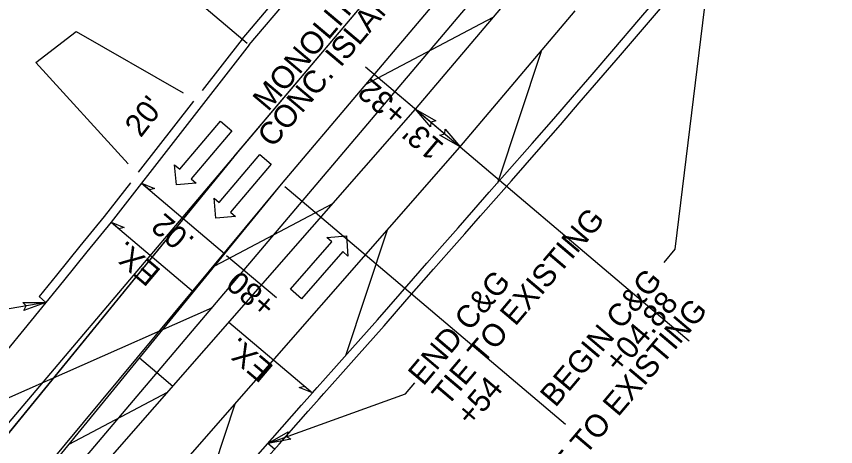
# Model space of a CAD drawing. Extents: x 1761082 to 1764358, y 421907 to 425434.
# Drawn here: x 1762006.6 to 1762189, y 422771.8 to 422867.6 of the extents above; entities that cross this region are included whole.
import ezdxf

# ---------------------------------------------------------------- set-up
doc = ezdxf.new("R2010")
doc.units = 0
for name, color, linetype in [('MARK HOOKS CENTER STRAIGHT LEFT TURN ARROW CELL', 7, 'Continuous'), ('MARK LEFT TURN ARROW CELL', 7, 'Continuous'), ('MARK ONLY WORD SYMBOL CELL', 7, 'Continuous'), ('MARK STRAIGHT RIGHT ARROW CELL', 7, 'Continuous'), ('MARK UTURN ARROW CELL', 7, 'Continuous'), ('Prop Conc Driveway', 7, 'Continuous'), ('Prop Mkg 3ft Min Skp 3ft Wide White', 7, 'Continuous'), ('Prop Mkg 3ft Min Skp 9ft Wide White', 7, 'Continuous'), ('Prop Mkg Min Skp 6ft Yellow', 7, 'Continuous'), ('Prop Mkg Skp Wht', 7, 'Continuous'), ('Prop Mkg Solid White Multiple Diagonals V8i', 7, 'Continuous'), ('Prop Mkg Solid Yel Skip LT', 7, 'Continuous'), ('Prop Mkg Solid Yel Skip RT', 7, 'Continuous'), ('Prop Mkg Solid Yellow Diagonals', 7, 'Continuous'), ('Prop Mkg Solid Yellow Edge Line', 7, 'Continuous'), ('Prop Mkg Solid Yellow Lane Line', 7, 'Continuous'), ('Scratch_Level_0', 7, 'Continuous'), ('Scratch_Level_5', 7, 'Continuous')]:
    doc.layers.add(name, color=color, linetype=linetype)

msp = doc.modelspace()

# ---------------------------------------------------------------- linework, layer by layer
at = {"layer": 'MARK HOOKS CENTER STRAIGHT LEFT TURN ARROW CELL'}
msp.add_line((1762070.2, 422826.39), (1762066.38, 422829.62), dxfattribs=at)
at = {"layer": 'MARK LEFT TURN ARROW CELL'}
for p, q in [((1762056.89, 422862.51), (1762067.26, 422874.75)), ((1762056.89, 422862.51), (1762047.97, 422851.06)), ((1762031.99, 422830.55), (1762026.12, 422823.02)), ((1762013.19, 422803.91), (1762011.66, 422805.21)), ((1762064.09, 422771.27), (1762062.57, 422772.56))]:
    msp.add_line(p, q, dxfattribs=at)
msp.add_lwpolyline([(1762026.12, 422823.02), (1762020.74, 422816.45), (1762015.52, 422809.98), (1762011.66, 422805.21)], dxfattribs=at)
at = {"layer": 'MARK ONLY WORD SYMBOL CELL'}
msp.add_line((1762033.83, 422832.91), (1762046.12, 422848.69), dxfattribs=at)
at = {"layer": 'MARK STRAIGHT RIGHT ARROW CELL'}
msp.add_line((1761294.53, 421910.78), (1762672.97, 423537.92), dxfattribs=at)
at = {"layer": 'MARK UTURN ARROW CELL'}
msp.add_lwpolyline([(1762050.16, 422802.74), (1761885.75, 422730.03), (1761804.33, 422633.93)], dxfattribs=at)
at = {"layer": 'Prop Conc Driveway'}
for p, q in [((1762010.93, 422857.29), (1762019.93, 422864.21)), ((1762019.93, 422864.21), (1762043.76, 422850.54)), ((1762031.47, 422834.76), (1762010.93, 422857.29))]:
    msp.add_line(p, q, dxfattribs=at)
at = {"layer": 'Prop Mkg 3ft Min Skp 3ft Wide White'}
msp.add_line((1761294.53, 421910.78), (1762672.97, 423537.92), dxfattribs=at)
at = {"layer": 'Prop Mkg 3ft Min Skp 9ft Wide White'}
for points in [[(1762074.01, 422782.47), (1762075.07, 422783.67), (1762078.74, 422787.78), (1762082.33, 422791.8), (1762088.47, 422798.73), (1762093.54, 422804.54), (1762099.47, 422811.3), (1762102.88, 422815.18), (1762106.42, 422819.2), (1762109.92, 422823.18), (1762113.38, 422827.1), (1762116.8, 422830.99), (1762122.94, 422837.96), (1762127.73, 422843.46), (1762131.92, 422848.3), (1762136.29, 422853.34), (1762141.13, 422858.95), (1762152.67, 422872.49)], [(1762006.07, 422705.23), (1762010.45, 422710.2), (1762014.62, 422714.93), (1762018.46, 422719.3), (1762021.98, 422723.3), (1762028.23, 422730.42), (1762034.5, 422737.58), (1762041.01, 422745.03), (1762044.41, 422748.92), (1762047.93, 422752.93), (1762051.57, 422757.05), (1762055.18, 422761.15), (1762058.64, 422765.08), (1762065.09, 422772.41), (1762071.58, 422779.74), (1762074.01, 422782.47)]]:
    msp.add_lwpolyline(points, dxfattribs=at)
at = {"layer": 'Prop Mkg Skp Wht'}
for q in [(1762092.94, 422901.97), (1762027.69, 422821.77)]:
    msp.add_line((1762058.44, 422861.25), q, dxfattribs=at)
for points in [[(1762072.51, 422783.8), (1762073.58, 422785), (1762077.25, 422789.11), (1762080.84, 422793.13), (1762086.97, 422800.06), (1762092.04, 422805.85), (1762097.97, 422812.62), (1762101.38, 422816.5), (1762104.92, 422820.52), (1762108.42, 422824.5), (1762111.88, 422828.43), (1762115.3, 422832.31), (1762121.43, 422839.28), (1762126.22, 422844.77), (1762130.41, 422849.61), (1762134.78, 422854.65), (1762139.61, 422860.25), (1762145.2, 422866.81), (1762151.14, 422873.79), (1762157.03, 422880.67), (1762161.8, 422886.24)], [(1762027.69, 422821.77), (1762022.3, 422815.19), (1762017.07, 422808.73), (1762011.57, 422801.92), (1762008.28, 422797.88), (1762004.62, 422793.41)], [(1762004.57, 422706.55), (1762008.95, 422711.52), (1762013.12, 422716.25), (1762016.96, 422720.62), (1762020.47, 422724.62), (1762026.72, 422731.74), (1762032.99, 422738.9), (1762039.5, 422746.35), (1762042.91, 422750.24), (1762046.43, 422754.25), (1762050.07, 422758.38), (1762053.68, 422762.47), (1762057.14, 422766.4), (1762063.59, 422773.73), (1762070.08, 422781.07), (1762072.51, 422783.8)]]:
    msp.add_lwpolyline(points, dxfattribs=at)
at = {"layer": 'Prop Mkg Solid White Multiple Diagonals V8i'}
for p, q in [((1761636.39, 422342), (1762107.89, 422898.74)), ((1762156.41, 422795.29), (1762090.88, 422850.81)), ((1761847.66, 422582.27), (1762056.32, 422837.86)), ((1761650.04, 422330.43), (1762065.62, 422830.27)), ((1762128.83, 422776.72), (1762070.2, 422826.39))]:
    msp.add_line(p, q, dxfattribs=at)
at = {"layer": 'Prop Mkg Solid Yel Skip RT'}
for p, q in [((1762037.29, 422879.17), (1762057.99, 422861.63)), ((1762084.34, 422856.34), (1762094.68, 422847.59)), ((1762095.46, 422846.93), (1762105.38, 422838.52)), ((1762053.42, 422814.39), (1762064.49, 422805.01))]:
    msp.add_line(p, q, dxfattribs=at)
for points in [[(1762161.8, 422886.24), (1762153.19, 422815.74), (1762150.72, 422812.83)], [(1762013.19, 422803.91), (1761904.06, 422785.03), (1761901.46, 422781.96)], [(1762062.57, 422772.56), (1762093.26, 422783.58), (1762095.3, 422785.99)]]:
    msp.add_lwpolyline(points, dxfattribs=at)
at = {"layer": 'Prop Mkg Solid Yellow Diagonals'}
for p, q in [((1762042.97, 422833.57), (1762052.03, 422844.24)), ((1762052.03, 422844.24), (1762054.55, 422842.1)), ((1762054.55, 422842.1), (1762045.49, 422831.43)), ((1762051.76, 422826.15), (1762060.82, 422836.82)), ((1762060.82, 422836.82), (1762063.34, 422834.69)), ((1762042.23, 422830.06), (1762041.83, 422834.54)), ((1762041.83, 422834.54), (1762042.97, 422833.57)), ((1762063.34, 422834.69), (1762054.28, 422824.02)), ((1762045.49, 422831.43), (1762046.63, 422830.46)), ((1762046.63, 422830.46), (1762042.23, 422830.06)), ((1762051.02, 422822.65), (1762050.62, 422827.12)), ((1762050.62, 422827.12), (1762051.76, 422826.15)), ((1762054.28, 422824.02), (1762055.42, 422823.04)), ((1762055.42, 422823.04), (1762051.02, 422822.65)), ((1762075.7, 422818.4), (1762080.1, 422818.72)), ((1762075.7, 422818.4), (1762080.1, 422818.72)), ((1762076.82, 422817.41), (1762075.7, 422818.4)), ((1762076.82, 422817.41), (1762075.7, 422818.4)), ((1762080.1, 422818.72), (1762080.43, 422814.24)), ((1762080.1, 422818.72), (1762080.43, 422814.24)), ((1762067.6, 422806.88), (1762076.82, 422817.41)), ((1762067.6, 422806.88), (1762076.82, 422817.41)), ((1762079.31, 422815.23), (1762070.08, 422804.71)), ((1762079.31, 422815.23), (1762070.08, 422804.71)), ((1762080.43, 422814.24), (1762079.31, 422815.23)), ((1762080.43, 422814.24), (1762079.31, 422815.23)), ((1762070.08, 422804.71), (1762067.6, 422806.88)), ((1762070.08, 422804.71), (1762067.6, 422806.88))]:
    msp.add_line(p, q, dxfattribs=at)
at = {"layer": 'Prop Mkg Solid Yellow Edge Line'}
for q in [(1762107.89, 422898.74), (1761848.88, 422583.77)]:
    msp.add_line((1762055.03, 422836.33), q, dxfattribs=at)
at = {"layer": 'Prop Mkg Solid Yellow Lane Line'}
for points in [[(1762098.78, 422842.96), (1762095.46, 422846.93), (1762099.96, 422844.3), (1762098.88, 422844.03)], [(1762102.05, 422842.49), (1762105.38, 422838.52), (1762100.88, 422841.15), (1762101.96, 422841.42)], [(1762008.01, 422803.91), (1762013.19, 422803.91), (1762008.29, 422802.14), (1762008.77, 422803.15)], [(1762067.67, 422773.46), (1762062.57, 422772.56), (1762067.09, 422775.15), (1762066.78, 422774.08)]]:
    msp.add_lwpolyline(points, close=True, dxfattribs=at)
at = {"layer": 'Scratch_Level_0'}
for p, q in [((1762065.62, 422830.27), (1762144.83, 422923.77)), ((1762095.46, 422846.93), (1762127.21, 422884.4)), ((1762084.36, 422852.39), (1762112.78, 422867.37)), ((1762105.31, 422838.44), (1762131, 422868.77)), ((1762123.4, 422859.79), (1762113.68, 422830.47)), ((1761856.89, 422574.6), (1762095.46, 422846.93)), ((1761842.22, 422538.12), (1762105.31, 422838.44)), ((1761856.89, 422574.6), (1762065.62, 422830.27)), ((1762050.77, 422812.08), (1762077.08, 422825.95)), ((1762089.13, 422819.98), (1762079.88, 422792.06)), ((1762037.88, 422788.24), (1762033.99, 422791.53)), ((1762041.42, 422785.24), (1762037.88, 422788.24)), ((1762018.37, 422772.39), (1762040.28, 422783.94)), ((1762055.25, 422781.3), (1762046.2, 422753.98))]:
    msp.add_line(p, q, dxfattribs=at)
at = {"layer": 'Scratch_Level_5'}
for p, q in [((1762034.45, 422830.46), (1762052.97, 422814.77)), ((1762027.69, 422821.77), (1762046.01, 422806.25)), ((1762053.94, 422799.53), (1762072.51, 422783.8))]:
    msp.add_line(p, q, dxfattribs=at)
for points in [[(1762034.45, 422830.46), (1762037.39, 422829.28), (1762036.22, 422828.96)], [(1762027.69, 422821.77), (1762030.62, 422820.6), (1762029.45, 422820.28)], [(1762072.51, 422783.8), (1762069.58, 422784.98), (1762070.75, 422785.29)]]:
    msp.add_lwpolyline(points, close=True, dxfattribs=at)

# ---------------------------------------------------------------- texts
at = {"layer": 'Prop Mkg Min Skp 6ft Yellow'}
for s, p in [('.02', (1762046.56, 422818.04)), ('EX.', (1762039.05, 422810.99)), ('EX.', (1762064.14, 422789.57))]:
    msp.add_text(s, height=5, rotation=139.7301, dxfattribs=at).set_placement(p)
at = {"layer": 'Prop Mkg Solid Yel Skip LT'}
for s, rotation, p in [('MONOLITHIC', 49.892, (1762062.64, 422846.22)), ('CONC. ISLAND', 49.892, (1762063.68, 422838.14)), ('+32', 139.7301, (1762094.06, 422846.59)), ("20'", 52.0751, (1762034.29, 422840.41)), ("13'", 139.7301, (1762102.1, 422838.93)), ('TIE TO EXISTING', 49.7301, (1762102.54, 422780.6)), ('BEGIN C&G', 49.7301, (1762126.6, 422780.38)), ('+80', 139.7301, (1762064.83, 422803.92)), ('END C&G', 49.7301, (1762097.2, 422785.13)), ('+04.88', 49.7301, (1762140.86, 422787.93)), ('TIE TO EXISTING', 49.7301, (1762125.42, 422760.43)), ('+54', 49.7301, (1762107.88, 422776.08))]:
    msp.add_text(s, height=5, rotation=rotation, dxfattribs=at).set_placement(p)

doc.saveas('drawing.dxf')
